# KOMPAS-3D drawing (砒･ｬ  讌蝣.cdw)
File: created 06.12.2016 20:32:03, last saved 20.12.2016 18:02:23.
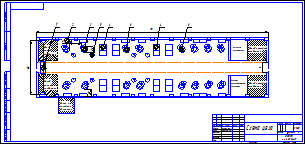
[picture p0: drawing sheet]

Sheet 1: A4x3, landscape

Title block, sheet 1: name: Схема цеха; scale: 1:150; sheets: 1; organisation: СПБПУ / гр. 43314/1; sheet format: A4 3; stored path: C:\Users\nikit\OneDrive\Документы\Лабораторные\4 курс\схема цеха.cdw; drawn by: Сидоров Н.А.; checked by: Кисленков В.В.

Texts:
  Никита
  Участок
  дробеструйной
  обработки
  Экспресс-
  лаборатория
  Склад готовой
  продукции
  Склад
  сырой
  Ванна с
  газовыми
  баллонами
  Стили документа
Dimensions and other numbers on the sheet: 12; 3; 2,5; 1,2; 1,5; 72; 1; 2; 4; 5; 6; 1:150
